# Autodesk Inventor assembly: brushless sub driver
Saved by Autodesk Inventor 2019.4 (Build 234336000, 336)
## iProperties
Created: 2020-10
Part Number: brushless sub driver
Document SubType Name: Assembly
Designer: Administrator
Title: brushless sub driver v1
Author: Administrator
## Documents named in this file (3)
- c:\worker\convert-fusion-r08\tmp\job-1\365\output\files\38382621-2638-444d-8690-1a65019e5fce\04471595-42d5-4aec-981a-0f0823f4641f.zip.iam
- c:\worker\convert-fusion-r08\tmp\job-1\365\output\files\38382621-2638-444d-8690-1a65019e5fce\Board.ipt
- c:\worker\convert-fusion-r08\tmp\job-1\365\output\files\38382621-2638-444d-8690-1a65019e5fce\Packages.iam
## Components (2 placed, 2 different names)
1. Board:1
2. Packages:1 [sub-assembly]
